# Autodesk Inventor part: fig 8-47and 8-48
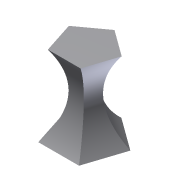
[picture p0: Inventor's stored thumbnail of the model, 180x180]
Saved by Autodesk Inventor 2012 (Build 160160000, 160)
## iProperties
Shininess: 64.0
Length Units: 11269
Angle Units: 11279
Time Units: 11290
Mass Units: 11283
Length Display Precision: 3
Angle Display Precision: 2
Compacted: True
Part Number: fig 8-47and 8-48
Document SubType Name: Modeling
Created: 2002-12
Designer: deepak
Density: 1 g/cm^3
Material: Default
Density: 0.0
Volumn: 0.0
Area: 0.0
PropertySet Name: Model Information
Control State: 0
Master: False
Checked Out: False
Author: deepak
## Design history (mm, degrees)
sketch "Sketch1"
  geometry: L1 (0, 21.819)-(20.751, 6.743); L2 (20.751, 6.743)-(12.825, -17.652); L3 (12.825, -17.652)-(-12.825, -17.652); L4 (-12.825, -17.652)-(-20.751, 6.743); L5 (-20.751, 6.743)-(0, 21.819); 1 further point
  constraints: 10 end point, 9 other
workplane "Work Plane1"
sketch "Sketch2"
  geometry: L1 (0, 8.24)-(7.836, 2.546); L2 (7.836, 2.546)-(4.843, -6.666); L3 (4.843, -6.666)-(-4.843, -6.666); L4 (-4.843, -6.666)-(-7.836, 2.546); L5 (-7.836, 2.546)-(0, 8.24); 1 further point
  constraints: 10 end point, 9 other
workplane "Work Plane2"
sketch "Sketch3"
  geometry: L1 (0, 17.494)-(16.637, 5.406); L2 (16.637, 5.406)-(10.283, -14.153); L3 (10.283, -14.153)-(-10.283, -14.153); L4 (-10.283, -14.153)-(-16.637, 5.406); L5 (-16.637, 5.406)-(0, 17.494); 1 further point
  constraints: 10 end point, 9 other
loft "Loft4" sketch "Sketch3" dims "d20" = 0, "d21" = 90 deg, "d22" = 0, "d23" = 90 deg, "d24" = 0, "d25" = 90 deg
body "Solid1"
other parameters: "d0" = 25, "d1" = 25
